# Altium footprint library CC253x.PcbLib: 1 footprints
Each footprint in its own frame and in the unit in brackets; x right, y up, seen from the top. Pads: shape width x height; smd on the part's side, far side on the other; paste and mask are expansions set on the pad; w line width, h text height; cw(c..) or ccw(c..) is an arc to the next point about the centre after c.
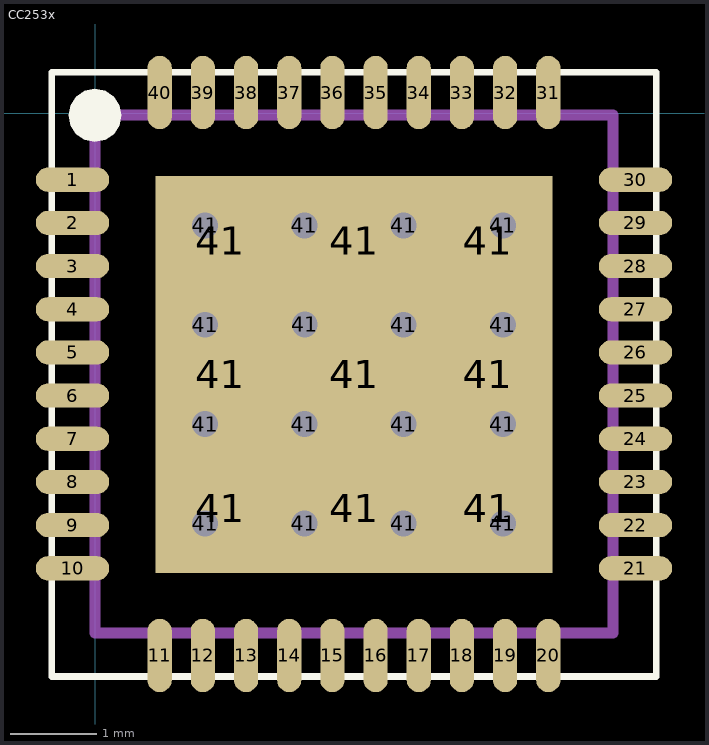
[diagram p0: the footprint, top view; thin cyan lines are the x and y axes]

## CC253x [mm]
pads (66):
  oval 0.85x0.28 smd paste+0 mask+0.14: 1(-0.263,-0.768) 2(-0.263,-1.268) 3(-0.263,-1.768) 4(-0.263,-2.268) 5(-0.263,-2.768) 6(-0.263,-3.268) 7(-0.263,-3.768) 8(-0.263,-4.268) 9(-0.263,-4.768) 10(-0.263,-5.268) 21(6.257,-5.268) 22(6.257,-4.768) 23(6.257,-4.268) 24(6.257,-3.768) 25(6.257,-3.268) 26(6.257,-2.768) 27(6.257,-2.268) 28(6.257,-1.768) 29(6.257,-1.268) 30(6.257,-0.768)
  oval 0.28x0.85 smd paste+0 mask+0.14: 11(0.747,-6.278) 12(1.247,-6.278) 13(1.747,-6.278) 14(2.247,-6.278) 15(2.747,-6.278) 16(3.247,-6.278) 17(3.747,-6.278) 18(4.247,-6.278) 19(4.747,-6.278) 20(5.247,-6.278) 31(5.247,0.242) 32(4.747,0.242) 33(4.247,0.242) 34(3.747,0.242) 35(3.247,0.242) 36(2.747,0.242) 37(2.247,0.242) 38(1.747,0.242) 39(1.247,0.242) 40(0.747,0.242)
  round 0.381 hole 0.3 paste+0 mask+0: 41(1.272,-4.748) 41(1.272,-3.598) 41(1.272,-2.448) 41(1.272,-1.298) 41(2.422,-4.748) 41(2.422,-3.598) 41(2.422,-1.298) 41(2.427,-2.443) 41(3.572,-4.748) 41(3.572,-3.598) 41(3.572,-2.448) 41(3.572,-1.298) 41(4.722,-4.748) 41(4.722,-3.598) 41(4.722,-2.448) 41(4.722,-1.298)
  rect 1.1x1.1 smd paste+0 mask+0: 41(1.447,-4.573) 41(1.447,-3.023) 41(1.447,-1.473) 41(2.997,-4.573) 41(2.997,-3.023) 41(2.997,-1.473) 41(4.547,-4.573) 41(4.547,-3.023) 41(4.547,-1.473)
  rect 4.6x4.6 smd paste-4.6 mask+0: 41(2.997,-3.023)
Top Overlay:
  region: -0.003,-0.328 -0.12,-0.305 -0.219,-0.239 -0.285,-0.14 -0.309,-0.023 -0.285,0.094 -0.219,0.194 -0.12,0.26 -0.003,0.283 0.114,0.26 0.213,0.194 0.28,0.094 0.303,-0.023 0.28,-0.14 0.213,-0.239 0.114,-0.305
  lines w0.08: -0.503,-6.523 6.497,-6.523 6.497,0.477 -0.503,0.477 -0.503,-6.523
Mechanical 2:
  lines w0.127: -0.003,-6.018 -0.003,-0.018 5.997,-0.018 5.997,-6.018 -0.003,-6.018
